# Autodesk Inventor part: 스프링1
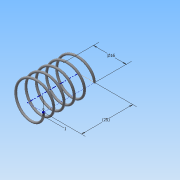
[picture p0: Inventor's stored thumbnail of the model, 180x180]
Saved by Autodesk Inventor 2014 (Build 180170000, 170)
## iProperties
Created: 2015-06
Part Number: 스프링1
Material: 강철, 연강
Document SubType Name: Modeling
Designer: Administrator
Density: 7.86 g/cm^3
Appearance: 강철
Mass: 1.53479 g
Surface Area: 7.89194 cm^2
Volume: 0.195266 cm^3
Author: Administrator
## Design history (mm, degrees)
sketch "스케치1"
  geometry: L1 (0, 0)-(8, 0); L2 (8, 0)-(8, 21.5); L3 (8, 21.5)-(0, 21.5); L4 (0, 21.5)-(0, 0); C1 r 0.5 at (8, 0)
  constraints: 8 end point, 2 parallel, 1 centre point, 1 coincident, 1 horizontal, 1 perpendicular
  dimensions: "d0" = 21.5 distance of L1.end L2.end (derived); "d1" = 16 diameter of L2 L4; "d2" = 1 diameter of C1
feature "코일1" sketch "스케치1" pitch "d3" = 10; turns "d5" = 5; dims "d4" = 21.5 (= d0), "d6" = 0, angle "d7" = 90 deg, angle "d8" = 90 deg, "d9" = 0, "d10" = 0
sketch "스케치2"
  geometry: L1 (-8.5, 0)-(-7.5, 0) reference; 1 further point
  constraints: 1 horizontal alignment
extrude "돌출1" cut sketch "스케치2" stored distance "d11" = 10; taper "d12" = 0 deg
node "작업 평면1"
sketch "스케치3"
  geometry: L1 (-7.5, 0)-(-8.5, 0) reference; 1 further point
  constraints: 1 horizontal alignment
extrude "돌출2" cut sketch "스케치3" stored distance "d14" = 10; taper "d15" = 0 deg
node "솔리드1"
node "절단 모서리 투영1"
node "절단 모서리 투영2"
other parameters: "d13" = 21.5 (= d0)
